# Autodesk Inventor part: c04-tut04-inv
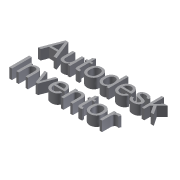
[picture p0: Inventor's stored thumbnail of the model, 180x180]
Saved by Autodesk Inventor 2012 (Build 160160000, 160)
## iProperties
Created: 2010-02
Part Number: c04-tut04-inv
Document SubType Name: Modeling
Designer: CADSoft
Density: 1 g/cm^3
Material: Default
Author: CADSoft
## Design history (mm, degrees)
sketch "Sketch1"
  geometry: L1 (-8.398, 18.152)-(22.665, 18.152); L2 (22.665, 18.152)-(22.665, 5.204); L3 (22.665, 5.204)-(-8.398, 5.204); L4 (-8.398, 5.204)-(-8.398, 18.152); 1 further point
  constraints: 2 other
extrude "Extrusion1" new body sketch "Sketch1" distance "d0" = 2.5; taper "d1" = 0 deg
body "Solid1"
